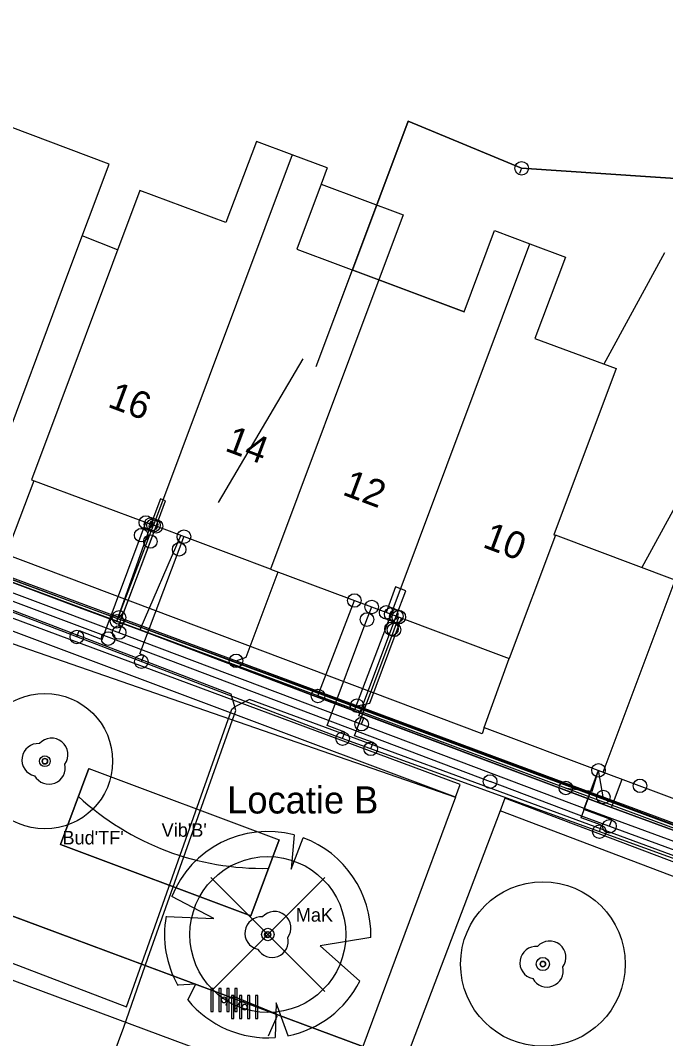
# Model space of a CAD drawing. Extents: x 192672 to 192910, y 446344 to 446512.
# Drawn here: x 192789.96 to 192813.76, y 446380.14 to 446417.71 of the extents above; entities that cross this region are included whole.
import ezdxf

# ---------------------------------------------------------------- set-up
doc = ezdxf.new("R2010")
doc.units = 0
for name, color, linetype in [('( Toegevoegd 29-11-2021 14_41_42) wegdeel vlak', 7, 'Continuous'), ('B-GV-GR-BOOM-S', 7, 'Continuous'), ('B-GV-KG-GRENS_WERKGRENS-G', 7, 'Continuous'), ('B-OI-KL-()_PUNTVANLEVERING_WATER-S', 7, 'Continuous'), ('B-OI-KL-BUISLEIDING_OLIEGASCHEMICALIEN_GASLAGEDRUK-G', 7, 'Continuous'), ('B-OI-KL-DATA-G', 7, 'Continuous'), ('B-OI-KL-DATA_GTWP-S', 7, 'Continuous'), ('B-OI-KL-DATA_HULPSTUK-S', 7, 'Continuous'), ('B-OI-KL-DATA_KABELBED-G', 7, 'Continuous'), ('B-OI-KL-DATA_MOF-S', 7, 'Continuous'), ('B-OI-KL-ET_LS-G', 7, 'Continuous'), ('B-OI-KL-ET_LS_AARDING-S', 7, 'Continuous'), ('B-OI-KL-ET_LS_DELIVERYPOINT-S', 7, 'Continuous'), ('B-OI-KL-ET_LS_MOF-S', 7, 'Continuous'), ('B-OI-KL-ET_MS-G', 7, 'Continuous'), ('B-OI-KL-GAS_LD_AFTAKZADEL-S', 7, 'Continuous'), ('B-OI-KL-GAS_LD_DELIVERYPOINT-S', 7, 'Continuous'), ('B-OI-KL-GAS_LD_OVERGANGSSTUK-S', 7, 'Continuous'), ('B-OI-KL-WATER-G', 7, 'Continuous'), ('B-OI-RI-RIOOLVRIJVERVAL-G', 7, 'Continuous'), ('boom', 7, 'Continuous'), ('Default', 7, 'Continuous'), ('huisnummerreeks BGT', 7, 'Continuous'), ('kant verharding', 7, 'Continuous'), ('kolk', 7, 'Continuous'), ('Luifel', 7, 'Continuous'), ('N-GV-GR-BEPLANTING-G', 7, 'Continuous'), ('N-GV-GR-BOOM-S', 7, 'Continuous'), ('pand op maaiveld vlak', 7, 'Continuous'), ('TEKST', 7, 'Continuous'), ('verkeerseiland - berm', 7, 'Continuous')]:
    doc.layers.add(name, color=color, linetype=linetype)

# ---------------------------------------------------------------- blocks, each defined once
blk = doc.blocks.new('B-OI-KL-DATA_HULPSTUK-S')
at = {"layer": 'Default'}
blk.add_circle((0, 0), 0.25, dxfattribs=at)
blk = doc.blocks.new('B-OI-KL-ET_LS_AARDING-S')
at = {"layer": 'Default'}
blk.add_circle((0, 0), 0.25, dxfattribs=at)
blk = doc.blocks.new('B-OI-KL-GAS_LD_AFTAKZADEL-S')
at = {"layer": 'Default'}
blk.add_circle((0, 0), 0.25, dxfattribs=at)
blk = doc.blocks.new('B-OI-KL-GAS_LD_DELIVERYPOINT-S')
at = {"layer": 'Default'}
blk.add_circle((0, 0), 0.25, dxfattribs=at)
blk = doc.blocks.new('B-OI-KL-GAS_LD_OVERGANGSSTUK-S')
at = {"layer": 'Default'}
blk.add_circle((0, 0), 0.25, dxfattribs=at)
blk = doc.blocks.new('B-OI-KL-ET_LS_DELIVERYPOINT-S')
at = {"layer": 'Default'}
blk.add_circle((0, 0), 0.25, dxfattribs=at)
blk = doc.blocks.new('B-OI-KL-ET_LS_MOF-S')
at = {"layer": 'Default'}
blk.add_circle((0, 0), 0.25, dxfattribs=at)
blk = doc.blocks.new('B-OI-KL-()_PUNTVANLEVERING_WATER-S')
at = {"layer": 'Default'}
blk.add_circle((0, 0), 0.25, dxfattribs=at)
blk = doc.blocks.new('B-OI-KL-DATA_GTWP-S')
at = {"layer": 'Default'}
blk.add_circle((0, 0), 0.25, dxfattribs=at)
blk = doc.blocks.new('B-OI-KL-DATA_MOF-S')
at = {"layer": 'Default'}
blk.add_circle((0, 0), 0.25, dxfattribs=at)

msp = doc.modelspace()

# ---------------------------------------------------------------- linework, layer by layer
at = {"layer": '( Toegevoegd 29-11-2021 14_41_42) wegdeel vlak'}
for points in [[(192807.071, 446391.618), (192806.989, 446391.38), (192789.199, 446398.084), (192788.212, 446398.449), (192770.35, 446405.075), (192770.467, 446405.283)], [(192806.008, 446389.049), (192806.18, 446389.51), (192788.76, 446395.99), (192788.604, 446395.572)], [(192821.627, 446377.648), (192822.094, 446377.471), (192824.128, 446382.832), (192807.836, 446389.015), (192807.659, 446388.548)]]:
    msp.add_lwpolyline(points, dxfattribs=at)
at = {"layer": 'B-GV-GR-BOOM-S'}
for p, q in [((192801.192, 446386.083), (192796.987, 446381.877)), ((192801.192, 446381.877), (192796.987, 446386.083))]:
    msp.add_line(p, q, dxfattribs=at)
for centre, radius in [((192790.866, 446390.376), 2.5), ((192790.866, 446390.376), 0.2), ((192799.089, 446383.98), 2.877), ((192809.234, 446382.89), 3.036), ((192799.089, 446383.98), 0.23), ((192809.234, 446382.89), 0.243)]:
    msp.add_circle(centre, radius, dxfattribs=at)
at = {"layer": 'B-GV-KG-GRENS_WERKGRENS-G'}
msp.add_lwpolyline([(192788.443, 446395.14), (192806.008, 446389.049), (192802.587, 446379.853), (192794.566, 446382.838), (192790.602, 446384.314), (192785.169, 446386.336)], close=True, dxfattribs=at)
at = {"layer": 'B-OI-KL-BUISLEIDING_OLIEGASCHEMICALIEN_GASLAGEDRUK-G'}
for points in [[(192825.926, 446382.49), (192824.393, 446382.916), (192820.049, 446384.609), (192801.561, 446391.312), (192784.629, 446397.804), (192756.601, 446408.196), (192751.089, 446410.462)], [(192794.417, 446398.717), (192794.592, 446399.185)], [(192792.045, 446394.961), (192792.135, 446395.194), (192792.977, 446394.871), (192794.417, 446398.717)], [(192795.818, 446398.192), (192795.993, 446398.661)], [(192794.426, 446394.048), (192794.515, 446394.281), (192794.374, 446394.336), (192795.818, 446398.192)], [(192802.745, 446395.602), (192802.919, 446396.068)], [(192801.849, 446391.208), (192801.934, 446391.443), (192801.28, 446391.688), (192802.745, 446395.602)], [(192803.745, 446395.225), (192803.92, 446395.693)], [(192802.883, 446390.833), (192802.968, 446391.068), (192802.282, 446391.317), (192803.745, 446395.225)], [(192811.316, 446387.775), (192811.401, 446388.01), (192810.649, 446388.283), (192811.285, 446390.04)]]:
    msp.add_lwpolyline(points, dxfattribs=at)
at = {"layer": 'B-OI-KL-DATA-G'}
for points in [[(192675.743, 446430.36), (192720.2, 446413.771), (192739.906, 446406.53), (192752.421, 446411.058), (192770.152, 446404.44), (192773.577, 446403.064), (192825.629, 446383.71), (192826.856, 446388.539), (192834.171, 446407.983), (192839.017, 446421.742), (192838.042, 446426.7), (192842.865, 446440.095), (192846.683, 446450.008), (192848.26, 446453.903), (192848.365, 446454.374), (192848.254, 446454.945), (192844.011, 446462.681), (192860.643, 446470.952)], [(192824.206, 446384.09), (192811.77, 446388.666), (192800.57, 446392.879), (192794.37, 446395.227), (192792.126, 446396.049), (192784.25, 446399.016), (192782.007, 446399.854), (192781.923, 446399.917), (192775.819, 446402.157), (192773.839, 446402.894), (192767.092, 446405.423), (192758.368, 446408.679), (192755.847, 446409.612), (192751.673, 446411.261), (192752.017, 446412.131), (192752.705, 446413.957), (192752.917, 446414.565), (192753.019, 446415.296), (192753.444, 446415.13)], [(192800.872, 446404.937), (192804.262, 446413.994), (192808.449, 446412.255), (192832.052, 446410.671)], [(192800.872, 446404.937), (192804.262, 446413.994), (192808.449, 446412.255), (192832.052, 446410.671)], [(192800.872, 446404.937), (192804.262, 446413.994), (192808.449, 446412.255), (192832.052, 446410.671)], [(192800.872, 446404.937), (192804.262, 446413.994), (192808.449, 446412.255), (192832.052, 446410.671)], [(192800.872, 446404.937), (192804.262, 446413.994), (192808.449, 446412.255), (192832.052, 446410.671)], [(192800.872, 446404.937), (192804.262, 446413.994), (192808.449, 446412.255), (192832.052, 446410.671)], [(192800.872, 446404.937), (192804.262, 446413.994), (192808.449, 446412.255), (192832.052, 446410.671)], [(192800.872, 446404.937), (192804.262, 446413.994), (192808.449, 446412.255)], [(192800.872, 446404.937), (192804.262, 446413.994), (192808.449, 446412.255)], [(192800.872, 446404.937), (192804.262, 446413.994), (192808.449, 446412.255)], [(192800.872, 446404.937), (192804.262, 446413.994), (192808.449, 446412.255)], [(192808.449, 446412.255), (192804.262, 446413.994), (192802.206, 446408.502), (192806.314, 446406.965)], [(192808.449, 446412.255), (192808.368, 446412.06)], [(192808.449, 446412.255), (192808.368, 446412.06)], [(192808.449, 446412.255), (192808.368, 446412.06)], [(192832.052, 446410.671), (192808.449, 446412.255)], [(192832.052, 446410.671), (192808.449, 446412.255)], [(192832.052, 446410.671), (192808.449, 446412.255)], [(192832.052, 446410.671), (192808.449, 446412.255)], [(192832.052, 446410.671), (192808.449, 446412.255)], [(192832.052, 446410.671), (192808.449, 446412.255)], [(192832.052, 446410.671), (192808.449, 446412.255)], [(192751.673, 446411.261), (192755.847, 446409.612), (192758.368, 446408.679), (192767.092, 446405.423), (192773.839, 446402.894), (192775.819, 446402.157), (192782.007, 446399.854), (192784.25, 446399.016), (192792.126, 446396.049), (192794.37, 446395.227), (192800.57, 446392.879), (192811.77, 446388.666), (192824.206, 446384.09), (192824.805, 446383.834)], [(192793.55, 446409.247), (192792.243, 446409.761)], [(192793.55, 446409.247), (192792.243, 446409.761)], [(192793.55, 446409.247), (192792.243, 446409.761)], [(192793.55, 446409.247), (192792.243, 446409.761)], [(192793.55, 446409.247), (192792.243, 446409.761)], [(192793.55, 446409.247), (192792.243, 446409.761)], [(192793.55, 446409.247), (192792.243, 446409.761)], [(192793.55, 446409.247), (192792.243, 446409.761)], [(192793.55, 446409.247), (192792.243, 446409.761)], [(192793.55, 446409.247), (192792.243, 446409.761)], [(192813.725, 446409.13), (192811.482, 446405.029)], [(192817.963, 446406.813), (192812.881, 446397.52)], [(192800.383, 446405.225), (192797.258, 446399.917)], [(192792.126, 446396.049), (192784.25, 446399.016)], [(192795.88, 446398.72), (192794.37, 446395.227)], [(192794.37, 446395.227), (192792.126, 446396.049)], [(192800.57, 446392.879), (192794.37, 446395.227)], [(192803.53, 446391.766), (192800.57, 446392.879)], [(192811.77, 446388.666), (192803.53, 446391.766)], [(192811.77, 446388.666), (192812.161, 446389.712)], [(192824.206, 446384.09), (192811.77, 446388.666)]]:
    msp.add_lwpolyline(points, dxfattribs=at)
at = {"layer": 'B-OI-KL-DATA_KABELBED-G'}
for points in [[(192802.206, 446408.502), (192804.262, 446413.994), (192808.449, 446412.255)], [(192808.449, 446412.255), (192808.368, 446412.06)], [(192832.052, 446410.671), (192808.449, 446412.255)], [(192821.01, 446385.323), (192810.079, 446389.386), (192802.298, 446392.278), (192800.939, 446392.783), (192793.524, 446395.538), (192789.077, 446397.191), (192779.512, 446400.781), (192775.099, 446402.438), (192774.537, 446402.649), (192761.96, 446407.369), (192758.326, 446408.733), (192752.386, 446410.963), (192751.738, 446411.209)], [(192793.55, 446409.247), (192792.243, 446409.761)], [(192813.725, 446409.13), (192811.482, 446405.029)], [(192800.872, 446404.937), (192802.206, 446408.502)], [(192802.206, 446408.502), (192806.314, 446406.965)], [(192817.963, 446406.813), (192812.881, 446397.52)], [(192800.383, 446405.225), (192797.258, 446399.917)], [(192793.524, 446395.538), (192794.78, 446399.115)], [(192793.524, 446395.538), (192794.873, 446399.08)], [(192800.939, 446392.783), (192802.281, 446396.306)], [(192800.939, 446392.783), (192802.298, 446392.278), (192803.639, 446395.798)], [(192810.079, 446389.386), (192811.052, 446389.272), (192811.285, 446390.04)]]:
    msp.add_lwpolyline(points, dxfattribs=at)
at = {"layer": 'B-OI-KL-ET_LS-G'}
for points in [[(192860.643, 446440.911), (192854.495, 446425.137), (192851.155, 446416.128), (192850.03, 446413.108), (192845.598, 446401.157), (192844.715, 446398.789), (192843.015, 446394.209), (192840.991, 446388.796), (192837.387, 446378.685), (192825.907, 446382.752), (192810.831, 446388.289), (192807.287, 446389.624)], [(192751.683, 446410.693), (192751.864, 446410.643), (192755.959, 446409.097), (192774.392, 446402.333), (192793.329, 446395.227), (192810.936, 446388.57), (192825.501, 446383.221), (192828.633, 446391.683), (192830.747, 446397.998), (192835.074, 446409.537), (192839.277, 446421.313), (192839.311, 446421.965), (192838.716, 446427.358), (192842.595, 446438.42)], [(192737.952, 446406.43), (192740.605, 446405.846), (192746.455, 446403.697), (192748.549, 446402.864), (192751.41, 446410.493), (192755.854, 446408.816), (192774.3, 446402.047), (192793.219, 446394.948), (192807.287, 446389.624)], [(192797.878, 446392.388), (192797.742, 446392.847), (192771.236, 446403.009), (192770.939, 446402.861)], [(192794.967, 446399.045), (192795.317, 446399.981), (192795.13, 446400.052), (192794.779, 446399.115)], [(192794.756, 446398.483), (192794.967, 446399.045)], [(192793.605, 446395.123), (192793.693, 446395.357), (192793.591, 446395.396), (192794.756, 446398.483)], [(192803.826, 446395.728), (192804.177, 446396.665), (192803.802, 446396.805), (192803.452, 446395.868)], [(192803.651, 446395.26), (192803.826, 446395.728)], [(192802.547, 446391.742), (192802.635, 446391.975), (192802.448, 446392.046), (192803.651, 446395.26)], [(192773.186, 446389.136), (192775.224, 446388.446), (192793.882, 446381.312), (192797.766, 446392.296), (192797.878, 446392.388)], [(192791.859, 446375.402), (192793.782, 446380.556), (192794.66, 446383.112), (192797.906, 446392.246), (192797.878, 446392.388)], [(192817.547, 446374.698), (192817.745, 446374.377), (192817.621, 446374.031), (192820.959, 446372.893), (192824.841, 446382.907), (192798.409, 446392.649), (192797.878, 446392.388)], [(192811.688, 446387.974), (192811.774, 446388.209), (192810.742, 446388.59), (192811.285, 446390.04)]]:
    msp.add_lwpolyline(points, dxfattribs=at)
at = {"layer": 'B-OI-KL-ET_MS-G'}
msp.add_lwpolyline([(192675.743, 446430.392), (192719.08, 446414.198), (192720.2, 446413.771), (192739.907, 446406.53), (192740.419, 446406.767), (192749.859, 446410.199), (192752.421, 446411.058), (192770.152, 446404.44), (192774.571, 446402.692), (192787.766, 446397.768), (192806.764, 446390.772), (192825.096, 446383.91)], dxfattribs=at)
at = {"layer": 'B-OI-KL-WATER-G'}
for points in [[(192742.681, 446414.565), (192743.85, 446414.136), (192825.105, 446383.994)], [(192789.096, 446397.352), (192789.267, 446397.55), (192790.468, 446400.729)], [(192793.601, 446395.681), (192793.777, 446395.876), (192794.967, 446399.045)], [(192797.916, 446394.08), (192798.289, 446394.209), (192799.468, 446397.36)], [(192802.376, 446392.425), (192802.85, 446392.517), (192804.024, 446395.654)], [(192811.46, 446389.055), (192811.285, 446390.04)]]:
    msp.add_lwpolyline(points, dxfattribs=at)
at = {"layer": 'B-OI-RI-RIOOLVRIJVERVAL-G'}
for points in [[(192799.385, 446381.058), (192797.865, 446381.679), (192797.668, 446381.619), (192797.532, 446381.363)], [(192798.238, 446381.526), (192798.034, 446381.458)], [(192798.034, 446381.458), (192797.907, 446381.223)], [(192799.42, 446380.96), (192799.096, 446380.235)], [(192799.385, 446381.058), (192799.42, 446380.96)]]:
    msp.add_lwpolyline(points, dxfattribs=at)
at = {"layer": 'boom'}
for centre in [(192790.866, 446390.376), (192799.091, 446383.98), (192809.234, 446382.89)]:
    msp.add_circle(centre, 0.1, dxfattribs=at)
for centre, radius, start, end in [((192790.616, 446390.426), 0.6, 85.137, 257.7544), ((192791.116, 446390.626), 0.6, 323.5446, 138.4658), ((192791.016, 446390.126), 0.6, 208.5058, 13.8356), ((192790.866, 446390.376), 0.1, 0, 180), ((192790.866, 446390.376), 0.1, 180, 0), ((192798.841, 446384.03), 0.6, 85.137, 257.7544), ((192799.341, 446384.23), 0.6, 323.5446, 138.4658), ((192799.241, 446383.73), 0.6, 208.5058, 13.8356), ((192799.091, 446383.98), 0.1, 0, 180), ((192799.091, 446383.98), 0.1, 180, 0), ((192809.484, 446383.14), 0.6, 323.5446, 138.4658), ((192808.984, 446382.94), 0.6, 85.137, 257.7544), ((192809.234, 446382.89), 0.1, 0, 180), ((192809.384, 446382.64), 0.6, 208.5058, 13.8356), ((192809.234, 446382.89), 0.1, 180, 0)]:
    msp.add_arc(centre, radius, start, end, dxfattribs=at)
at = {"layer": 'kant verharding'}
msp.add_line((192753.133, 446395.89), (192813.567, 446373.412), dxfattribs=at)
at = {"layer": 'kolk'}
for points in [[(192797.069, 446381.567), (192797.069, 446381.992), (192796.984, 446381.992), (192796.984, 446381.567), (192796.984, 446381.142), (192797.069, 446381.142)], [(192797.367, 446381.567), (192797.367, 446381.992), (192797.282, 446381.992), (192797.282, 446381.567), (192797.282, 446381.142), (192797.367, 446381.142)], [(192797.664, 446381.567), (192797.664, 446381.992), (192797.579, 446381.992), (192797.579, 446381.567), (192797.579, 446381.142), (192797.664, 446381.142)], [(192797.962, 446381.567), (192797.962, 446381.992), (192797.877, 446381.992), (192797.877, 446381.567), (192797.877, 446381.142), (192797.962, 446381.142)], [(192797.83, 446381.301), (192797.83, 446381.726), (192797.745, 446381.726), (192797.745, 446381.301), (192797.745, 446380.876), (192797.83, 446380.876)], [(192798.128, 446381.301), (192798.128, 446381.726), (192798.043, 446381.726), (192798.043, 446381.301), (192798.043, 446380.876), (192798.128, 446380.876)], [(192798.425, 446381.301), (192798.425, 446381.726), (192798.34, 446381.726), (192798.34, 446381.301), (192798.34, 446380.876), (192798.425, 446380.876)], [(192798.723, 446381.301), (192798.723, 446381.726), (192798.638, 446381.726), (192798.638, 446381.301), (192798.638, 446380.876), (192798.723, 446380.876)]]:
    msp.add_lwpolyline(points, close=True, dxfattribs=at)
for centre, start, end in [((192797.473, 446381.567), 0, 180), ((192797.473, 446381.567), 180, 0), ((192798.234, 446381.301), 0, 180), ((192798.234, 446381.301), 180, 0)]:
    msp.add_arc(centre, 0.1, start, end, dxfattribs=at)
at = {"layer": 'Luifel'}
msp.add_lwpolyline([(192801.06, 446411.669), (192804.079, 446410.539), (192803.18, 446408.138)], dxfattribs=at)
at = {"layer": 'N-GV-GR-BEPLANTING-G'}
msp.add_line((192792.487, 446390.112), (192799.51, 446387.48), dxfattribs=at)
msp.add_lwpolyline([(192798.464, 446384.668), (192791.442, 446387.3), (192792.487, 446390.112), (192799.51, 446387.48)], close=True, dxfattribs=at)
msp.add_lwpolyline([(192792.487, 446390.112), (192791.442, 446387.3), (192798.464, 446384.668), (192799.51, 446387.48)], dxfattribs=at)
msp.add_arc((192798.891, 446396.422), 10, 227.2483, 271.2985, dxfattribs=at)
at = {"layer": 'N-GV-GR-BOOM-S'}
for points in [[(192800.056, 446387.653), (192799.944, 446386.397), (192800.391, 446387.547)], [(192795.339, 446384.651), (192797.096, 446384.568), (192795.548, 446385.381)], [(192802.887, 446383.876), (192801.02, 446383.558), (192802.48, 446382.259)], [(192796.138, 446381.566), (192796.437, 446382.146), (192795.77, 446382.105)], [(192799.833, 446380.244), (192799.4, 446381.457), (192799.356, 446380.179)]]:
    msp.add_lwpolyline(points, dxfattribs=at)
msp.add_circle((192799.083, 446383.974), 0.113, dxfattribs=at)
for start, end in [(75.1844, 158.299), (358.5241, 69.9066), (169.749, 209.4302), (281.3601, 333.2046), (219.2667, 274.1068)]:
    msp.add_arc((192799.083, 446383.974), 3.805, start, end, dxfattribs=at)
at = {"layer": 'pand op maaiveld vlak'}
for p, q in [((192799.989, 446412.75), (192794.873, 446399.08)), ((192801.283, 446412.266), (192799.989, 446412.75)), ((192801.283, 446412.266), (192801.06, 446411.669)), ((192803.639, 446395.798), (192808.756, 446409.467)), ((192803.18, 446408.138), (192799.184, 446397.466)), ((192799.184, 446397.466), (192794.873, 446399.08)), ((192809.693, 446398.714), (192807.995, 446394.168)), ((192814.113, 446397.059), (192809.693, 446398.714)), ((192799.184, 446397.466), (192803.639, 446395.798)), ((192811.461, 446389.974), (192814.113, 446397.059)), ((192803.639, 446395.798), (192807.995, 446394.168)), ((192807.071, 446391.618), (192807.995, 446394.168)), ((192807.071, 446391.618), (192811.461, 446389.974)), ((192811.461, 446389.974), (192815.852, 446388.331))]:
    msp.add_line(p, q, dxfattribs=at)
for points in [[(192784.643, 446402.882), (192789.06, 446401.234), (192791.717, 446408.352), (192793.234, 446412.413), (192788.818, 446414.063)], [(192799.989, 446412.75), (192798.667, 446413.245), (192797.546, 446410.249), (192794.37, 446411.438), (192790.374, 446400.764), (192794.873, 446399.08)], [(192801.06, 446411.669), (192800.161, 446409.268), (192803.18, 446408.138)], [(192803.18, 446408.138), (192806.327, 446406.96), (192807.448, 446409.956), (192808.756, 446409.467)], [(192808.756, 446409.467), (192810.064, 446408.977), (192808.942, 446405.98), (192811.931, 446404.861), (192809.638, 446398.734), (192809.693, 446398.714)]]:
    msp.add_lwpolyline(points, dxfattribs=at)
at = {"layer": 'verkeerseiland - berm'}
for p, q in [((192806.008, 446389.049), (192788.604, 446395.572)), ((192806.008, 446389.049), (192802.587, 446379.853)), ((192807.659, 446388.548), (192804.14, 446379.275)), ((192785.169, 446386.336), (192802.587, 446379.853))]:
    msp.add_line(p, q, dxfattribs=at)
msp.add_lwpolyline([(192821.627, 446377.648), (192823.483, 446382.542), (192807.659, 446388.548)], dxfattribs=at)

# ---------------------------------------------------------------- block references
at = {"layer": 'B-OI-KL-()_PUNTVANLEVERING_WATER-S'}
for p in [(192793.601, 446395.681), (192797.916, 446394.08), (192802.376, 446392.425), (192811.46, 446389.055)]:
    msp.add_blockref('B-OI-KL-()_PUNTVANLEVERING_WATER-S', p, dxfattribs=at)
at = {"layer": 'B-OI-KL-DATA_GTWP-S'}
for p in [(192794.78, 446399.115), (192794.873, 446399.08), (192802.281, 446396.306), (192793.524, 446395.538), (192793.524, 446395.538), (192803.639, 446395.798), (192800.939, 446392.783), (192800.939, 446392.783), (192811.285, 446390.04), (192810.079, 446389.386)]:
    msp.add_blockref('B-OI-KL-DATA_GTWP-S', p, dxfattribs=at)
at = {"layer": 'B-OI-KL-DATA_HULPSTUK-S'}
msp.add_blockref('B-OI-KL-DATA_HULPSTUK-S', (192808.449, 446412.255), dxfattribs=at)
at = {"layer": 'B-OI-KL-DATA_MOF-S'}
for p in [(192793.524, 446395.538), (192800.939, 446392.783), (192810.079, 446389.386)]:
    msp.add_blockref('B-OI-KL-DATA_MOF-S', p, dxfattribs=at)
at = {"layer": 'B-OI-KL-ET_LS_AARDING-S'}
msp.add_blockref('B-OI-KL-ET_LS_AARDING-S', (192793.201, 446394.901), dxfattribs=at)
at = {"layer": 'B-OI-KL-ET_LS_DELIVERYPOINT-S'}
for p in [(192794.779, 446399.115), (192794.967, 446399.045), (192803.452, 446395.868), (192803.826, 446395.728), (192812.815, 446389.468)]:
    msp.add_blockref('B-OI-KL-ET_LS_DELIVERYPOINT-S', p, dxfattribs=at)
at = {"layer": 'B-OI-KL-ET_LS_MOF-S'}
for p in [(192794.756, 446398.483), (192803.651, 446395.26), (192793.605, 446395.123), (192802.547, 446391.742), (192811.285, 446390.04), (192807.287, 446389.624), (192811.688, 446387.974)]:
    msp.add_blockref('B-OI-KL-ET_LS_MOF-S', p, dxfattribs=at)
at = {"layer": 'B-OI-KL-GAS_LD_AFTAKZADEL-S'}
for p in [(192792.045, 446394.961), (192794.426, 446394.048), (192801.849, 446391.208), (192802.883, 446390.833), (192811.316, 446387.775)]:
    msp.add_blockref('B-OI-KL-GAS_LD_AFTAKZADEL-S', p, dxfattribs=at)
at = {"layer": 'B-OI-KL-GAS_LD_DELIVERYPOINT-S'}
for p in [(192794.592, 446399.185), (192795.993, 446398.661), (192802.919, 446396.068), (192803.92, 446395.693), (192811.285, 446390.04)]:
    msp.add_blockref('B-OI-KL-GAS_LD_DELIVERYPOINT-S', p, dxfattribs=at)
at = {"layer": 'B-OI-KL-GAS_LD_OVERGANGSSTUK-S'}
for p in [(192794.417, 446398.717), (192795.818, 446398.192), (192802.745, 446395.602), (192803.745, 446395.225)]:
    msp.add_blockref('B-OI-KL-GAS_LD_OVERGANGSSTUK-S', p, dxfattribs=at)

# ---------------------------------------------------------------- texts
at = {"layer": 'huisnummerreeks BGT'}
for s, p in [('16', (192793.142, 446403.465)), ('14', (192797.466, 446401.846)), ('12', (192801.801, 446400.223)), ('10', (192806.972, 446398.287))]:
    msp.add_text(s, height=1, rotation=339.5, dxfattribs=at).set_placement(p)
at = {"layer": 'TEKST'}
for s, height, p in [('Locatie B', 1, (192797.59, 446388.446)), ("Vib'B'", 0.5, (192795.171, 446387.586)), ("Bud'TF'", 0.5, (192791.514, 446387.304)), ('MaK', 0.5, (192800.119, 446384.454))]:
    msp.add_text(s, height=height, dxfattribs=at).set_placement(p)

doc.saveas('drawing.dxf')
